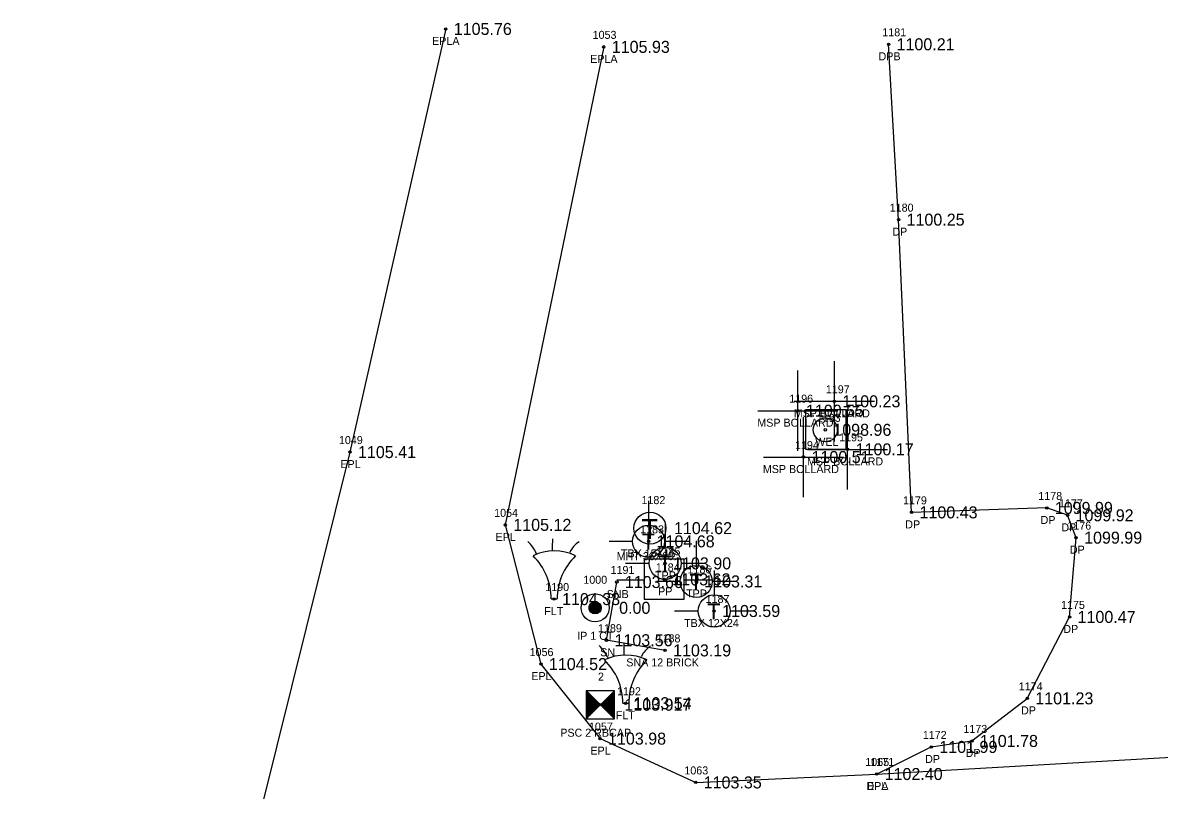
# Model space of a CAD drawing. Extents: x 1539151 to 1541799, y 1198646 to 1201165.
# Drawn here: x 1539356.2 to 1539498.1, y 1199362.1 to 1199457.9 of the extents above; entities that cross this region are included whole.
import ezdxf

# ---------------------------------------------------------------- set-up
doc = ezdxf.new("R2010")
doc.units = 0
for name, color, linetype in [('RD_EX_BldgApp', 7, 'Continuous'), ('RD_EX_BldgApp_txCode', 7, 'Continuous'), ('RD_EX_Driveway', 7, 'Continuous'), ('RD_EX_Driveway_txCode', 7, 'Continuous'), ('RD_EX_DV_Prop_txCode', 7, 'Continuous'), ('RD_EX_DV_PropPin', 7, 'Continuous'), ('RD_EX_Misc', 7, 'Continuous'), ('RD_EX_Misc_txCode', 7, 'Continuous'), ('RD_EX_Road', 7, 'Continuous'), ('RD_EX_Road_txCode', 7, 'Continuous'), ('RD_EX_SU_H2O', 7, 'Continuous'), ('RD_EX_SU_Telecom', 7, 'Continuous'), ('RD_EX_TX_BldgApp_ELEV', 7, 'Continuous'), ('RD_EX_TX_Driveway_ELEV', 7, 'Continuous'), ('RD_EX_TX_DV_Prop_ELEV', 7, 'Continuous'), ('RD_EX_TX_Misc_ELEV', 7, 'Continuous'), ('RD_EX_TX_Road_ELEV', 7, 'Continuous'), ('RD_EX_TX_UT_ELEV', 7, 'Continuous'), ('RD_EX_UT', 7, 'Continuous'), ('RD_EX_UT_txCode', 7, 'Continuous'), ('RD_HC_Survey', 7, 'Continuous'), ('RD_HC_Survey_ELEV', 7, 'Continuous'), ('RD_HC_txCode', 7, 'Continuous'), ('RD_SMD_Locator', 7, 'Continuous')]:
    doc.layers.add(name, color=color, linetype=linetype)

msp = doc.modelspace()

# ---------------------------------------------------------------- linework, layer by layer
at = {"layer": 'RD_EX_BldgApp'}
for p, q in [((1539422.2, 1199385.98), (1539422.95, 1199385.98)), ((1539431.13, 1199372.97), (1539431.88, 1199372.97))]:
    msp.add_line(p, q, dxfattribs=at)
msp.add_lwpolyline([(1539436.42, 1199379.55), (1539429.1, 1199380.82), (1539430.39, 1199388.09)], dxfattribs=at)
for centre, radius, start, end in [((1539384.5, 1199393.32), 37.88, 358.0671, 0.2715), ((1539415.89, 1199389.62), 4.89, 24.3279, 46.2665), ((1539422.58, 1199385.98), 6, 63.7794, 116.2206), ((1539427.47, 1199390.37), 3.28, 123.2906, 154.4886), ((1539414.7, 1199385.98), 7.5, 0, 45.8366), ((1539430.45, 1199385.98), 7.5, 134.1634, 180), ((1539393.43, 1199380.3), 37.88, 358.0671, 0.2715), ((1539424.82, 1199376.61), 4.89, 24.3279, 46.2665), ((1539436.4, 1199377.36), 3.28, 123.2906, 154.4886), ((1539431.51, 1199372.97), 6, 63.7794, 116.2206), ((1539423.63, 1199372.97), 7.5, 0, 45.8366), ((1539439.38, 1199372.97), 7.5, 134.1634, 180)]:
    msp.add_arc(centre, radius, start, end, dxfattribs=at)
at = {"layer": 'RD_EX_BldgApp_txCode'}
msp.add_circle((1539456.43, 1199407.1), 0.15, dxfattribs=at)
at = {"layer": 'RD_EX_Driveway'}
msp.add_lwpolyline([(1539462.84, 1199364.11), (1539469.67, 1199367.49), (1539474.74, 1199368.24), (1539481.66, 1199373.56), (1539486.94, 1199383.73), (1539487.76, 1199393.63), (1539486.69, 1199396.42), (1539484.1, 1199397.34), (1539467.2, 1199396.79), (1539465.58, 1199433.35), (1539464.33, 1199455.25)], dxfattribs=at)
at = {"layer": 'RD_EX_DV_PropPin'}
for p, q in [((1539426.94, 1199384.67), (1539426.94, 1199385.07)), ((1539426.98, 1199384.57), (1539426.98, 1199385.17)), ((1539427.01, 1199384.5), (1539427.01, 1199385.24)), ((1539427.05, 1199384.44), (1539427.05, 1199385.3)), ((1539427.08, 1199384.4), (1539427.08, 1199385.35)), ((1539427.12, 1199384.36), (1539427.12, 1199385.39)), ((1539427.15, 1199384.32), (1539427.15, 1199385.42)), ((1539427.19, 1199384.29), (1539427.19, 1199385.45)), ((1539427.22, 1199384.26), (1539427.22, 1199385.48)), ((1539427.26, 1199384.24), (1539427.26, 1199385.51)), ((1539427.29, 1199384.21), (1539427.29, 1199385.53)), ((1539427.33, 1199384.2), (1539427.33, 1199385.55)), ((1539427.36, 1199384.18), (1539427.36, 1199385.56)), ((1539427.4, 1199384.16), (1539427.4, 1199385.58)), ((1539427.43, 1199384.15), (1539427.43, 1199385.59)), ((1539427.47, 1199384.14), (1539427.47, 1199385.6)), ((1539427.5, 1199384.13), (1539427.5, 1199385.61)), ((1539427.54, 1199384.12), (1539427.54, 1199385.62)), ((1539427.57, 1199384.12), (1539427.57, 1199385.62)), ((1539427.61, 1199384.11), (1539427.61, 1199385.63)), ((1539427.64, 1199384.11), (1539427.64, 1199385.63)), ((1539427.68, 1199384.11), (1539427.68, 1199385.63)), ((1539427.71, 1199384.11), (1539427.71, 1199385.63)), ((1539427.75, 1199384.11), (1539427.75, 1199385.63)), ((1539427.78, 1199384.12), (1539427.78, 1199385.62)), ((1539427.82, 1199384.12), (1539427.82, 1199385.62)), ((1539427.85, 1199384.13), (1539427.85, 1199385.61)), ((1539427.89, 1199384.14), (1539427.89, 1199385.6)), ((1539427.92, 1199384.15), (1539427.92, 1199385.59)), ((1539427.96, 1199384.16), (1539427.96, 1199385.58)), ((1539427.99, 1199384.18), (1539427.99, 1199385.56)), ((1539428.03, 1199384.2), (1539428.03, 1199385.55)), ((1539428.06, 1199384.21), (1539428.06, 1199385.53)), ((1539428.1, 1199384.24), (1539428.1, 1199385.51)), ((1539428.13, 1199384.26), (1539428.13, 1199385.48)), ((1539428.17, 1199384.29), (1539428.17, 1199385.45)), ((1539428.2, 1199384.32), (1539428.2, 1199385.42)), ((1539428.24, 1199384.36), (1539428.24, 1199385.39)), ((1539428.27, 1199384.4), (1539428.27, 1199385.35)), ((1539428.31, 1199384.44), (1539428.31, 1199385.3)), ((1539428.34, 1199384.5), (1539428.34, 1199385.24)), ((1539428.38, 1199384.57), (1539428.38, 1199385.17)), ((1539428.41, 1199384.67), (1539428.41, 1199385.07))]:
    msp.add_line(p, q, dxfattribs=at)
for radius in [1.75, 0.761]:
    msp.add_circle((1539427.68, 1199384.87), radius, dxfattribs=at)
at = {"layer": 'RD_EX_Misc'}
for p, q in [((1539457.56, 1199405.66), (1539457.56, 1199415.66)), ((1539453.01, 1199404.49), (1539453.01, 1199414.49)), ((1539452.56, 1199410.66), (1539462.56, 1199410.66)), ((1539448.01, 1199409.49), (1539458.01, 1199409.49)), ((1539459.22, 1199399.66), (1539459.22, 1199409.66)), ((1539453.71, 1199398.7), (1539453.71, 1199408.7)), ((1539454.22, 1199404.66), (1539464.22, 1199404.66)), ((1539448.71, 1199403.7), (1539458.71, 1199403.7))]:
    msp.add_line(p, q, dxfattribs=at)
at = {"layer": 'RD_EX_Road'}
for points in [[(1539409.02, 1199457.17), (1539397.06, 1199404.32), (1539384.29, 1199353.07), (1539370.25, 1199298.34), (1539356.18, 1199244.03)], [(1539428.76, 1199454.93), (1539416.46, 1199395.23), (1539420.91, 1199377.84), (1539428.29, 1199368.53), (1539440.24, 1199363.06), (1539462.84, 1199364.11), (1539506.12, 1199366.59), (1539554.03, 1199368.02), (1539606.53, 1199370.48), (1539651.89, 1199372.76), (1539672.94, 1199372.91), (1539707.02, 1199374.85), (1539748.7, 1199377.62), (1539769.05, 1199378.19), (1539812.94, 1199380.16), (1539830.48, 1199381.23), (1539857.01, 1199382.87), (1539908.22, 1199385.45), (1539955.82, 1199389.74), (1539996.13, 1199397.4), (1540037.85, 1199410.51), (1540050.26, 1199415.61), (1540093.12, 1199444.78)]]:
    msp.add_lwpolyline(points, dxfattribs=at)
at = {"layer": 'RD_EX_SU_H2O'}
msp.add_lwpolyline([(1539453.98, 1199404.63), (1539453.98, 1199409.63), (1539458.98, 1199409.63), (1539458.98, 1199404.63)], close=True, dxfattribs=at)
msp.add_circle((1539456.43, 1199407.1), 1.5, dxfattribs=at)
at = {"layer": 'RD_EX_SU_Telecom'}
msp.add_circle((1539434.53, 1199394.82), 2, dxfattribs=at)
at = {"layer": 'RD_EX_UT'}
for p, q in [((1539434.36, 1199398.24), (1539434.36, 1199395.17)), ((1539436.42, 1199395.49), (1539436.42, 1199392.42)), ((1539440.31, 1199393.23), (1539440.31, 1199390.16)), ((1539429.43, 1199393.19), (1539432.36, 1199393.19)), ((1539436.36, 1199393.19), (1539439.43, 1199393.19)), ((1539431.49, 1199390.44), (1539434.42, 1199390.44)), ((1539438.82, 1199390.93), (1539433.82, 1199390.93)), ((1539433.82, 1199390.93), (1539433.82, 1199385.93)), ((1539438.42, 1199390.44), (1539441.49, 1199390.44)), ((1539438.82, 1199385.93), (1539438.82, 1199390.93)), ((1539442.54, 1199389.53), (1539442.54, 1199386.47)), ((1539430.39, 1199388.36), (1539433.86, 1199388.36)), ((1539435.38, 1199388.18), (1539438.31, 1199388.18)), ((1539438.75, 1199388.36), (1539442.39, 1199388.36)), ((1539442.31, 1199388.18), (1539445.38, 1199388.18)), ((1539433.82, 1199385.93), (1539438.82, 1199385.93)), ((1539437.61, 1199384.48), (1539440.54, 1199384.48)), ((1539444.54, 1199384.48), (1539447.61, 1199384.48))]:
    msp.add_line(p, q, dxfattribs=at)
for centre in [(1539434.36, 1199393.17), (1539436.42, 1199390.42), (1539440.31, 1199388.16), (1539442.54, 1199384.47)]:
    msp.add_circle(centre, 2, dxfattribs=at)
at = {"layer": 'RD_HC_Survey'}
for p, q in [((1539426.58, 1199374.52), (1539430.08, 1199371.02)), ((1539430.08, 1199374.52), (1539426.58, 1199371.02)), ((1539426.6, 1199374.49), (1539426.6, 1199371.04)), ((1539426.63, 1199374.47), (1539426.63, 1199371.07)), ((1539426.65, 1199374.44), (1539426.65, 1199371.09)), ((1539426.68, 1199374.42), (1539426.68, 1199371.12)), ((1539426.7, 1199374.39), (1539426.7, 1199371.14)), ((1539426.73, 1199374.37), (1539426.73, 1199371.17)), ((1539426.75, 1199374.34), (1539426.75, 1199371.19)), ((1539426.78, 1199374.32), (1539426.78, 1199371.21)), ((1539426.8, 1199374.29), (1539426.8, 1199371.24)), ((1539426.83, 1199374.27), (1539426.83, 1199371.26)), ((1539426.85, 1199374.24), (1539426.85, 1199371.29)), ((1539426.87, 1199374.22), (1539426.87, 1199371.31)), ((1539426.9, 1199374.2), (1539426.9, 1199371.34)), ((1539426.92, 1199374.17), (1539426.92, 1199371.36)), ((1539426.95, 1199374.15), (1539426.95, 1199371.39)), ((1539426.97, 1199374.12), (1539426.97, 1199371.41)), ((1539427, 1199374.1), (1539427, 1199371.44)), ((1539427.02, 1199374.07), (1539427.02, 1199371.46)), ((1539427.05, 1199374.05), (1539427.05, 1199371.49)), ((1539427.07, 1199374.02), (1539427.07, 1199371.51)), ((1539427.1, 1199374), (1539427.1, 1199371.54)), ((1539427.12, 1199373.97), (1539427.12, 1199371.56)), ((1539427.15, 1199373.95), (1539427.15, 1199371.59)), ((1539427.17, 1199373.92), (1539427.17, 1199371.61)), ((1539427.2, 1199373.9), (1539427.2, 1199371.64)), ((1539427.22, 1199373.87), (1539427.22, 1199371.66)), ((1539427.25, 1199373.85), (1539427.25, 1199371.69)), ((1539427.27, 1199373.82), (1539427.27, 1199371.71)), ((1539427.3, 1199373.8), (1539427.3, 1199371.73)), ((1539427.32, 1199373.77), (1539427.32, 1199371.76)), ((1539427.35, 1199373.75), (1539427.35, 1199371.78)), ((1539427.37, 1199373.73), (1539427.37, 1199371.81)), ((1539427.39, 1199373.7), (1539427.39, 1199371.83)), ((1539427.42, 1199373.68), (1539427.42, 1199371.86)), ((1539427.44, 1199373.65), (1539427.44, 1199371.88)), ((1539427.47, 1199373.63), (1539427.47, 1199371.91)), ((1539427.49, 1199373.6), (1539427.49, 1199371.93)), ((1539427.52, 1199373.58), (1539427.52, 1199371.96)), ((1539427.54, 1199373.55), (1539427.54, 1199371.98)), ((1539427.57, 1199373.53), (1539427.57, 1199372.01)), ((1539427.59, 1199373.5), (1539427.59, 1199372.03)), ((1539427.62, 1199373.48), (1539427.62, 1199372.06)), ((1539427.64, 1199373.45), (1539427.64, 1199372.08)), ((1539427.67, 1199373.43), (1539427.67, 1199372.11)), ((1539427.69, 1199373.4), (1539427.69, 1199372.13)), ((1539427.72, 1199373.38), (1539427.72, 1199372.16)), ((1539427.74, 1199373.35), (1539427.74, 1199372.18)), ((1539428.91, 1199373.35), (1539428.91, 1199372.18)), ((1539428.94, 1199373.38), (1539428.94, 1199372.16)), ((1539428.96, 1199373.4), (1539428.96, 1199372.13)), ((1539428.99, 1199373.43), (1539428.99, 1199372.11)), ((1539429.01, 1199373.45), (1539429.01, 1199372.08)), ((1539429.04, 1199373.48), (1539429.04, 1199372.06)), ((1539429.06, 1199373.5), (1539429.06, 1199372.03)), ((1539429.09, 1199373.53), (1539429.09, 1199372.01)), ((1539429.11, 1199373.55), (1539429.11, 1199371.98)), ((1539429.14, 1199373.58), (1539429.14, 1199371.96)), ((1539429.16, 1199373.6), (1539429.16, 1199371.93)), ((1539429.19, 1199373.63), (1539429.19, 1199371.91)), ((1539429.21, 1199373.65), (1539429.21, 1199371.88)), ((1539429.24, 1199373.68), (1539429.24, 1199371.86)), ((1539429.26, 1199373.7), (1539429.26, 1199371.83)), ((1539429.29, 1199373.73), (1539429.29, 1199371.81)), ((1539429.31, 1199373.75), (1539429.31, 1199371.78)), ((1539429.34, 1199373.77), (1539429.34, 1199371.76)), ((1539429.36, 1199373.8), (1539429.36, 1199371.73)), ((1539429.39, 1199373.82), (1539429.39, 1199371.71)), ((1539429.41, 1199373.85), (1539429.41, 1199371.69)), ((1539429.43, 1199373.87), (1539429.43, 1199371.66)), ((1539429.46, 1199373.9), (1539429.46, 1199371.64)), ((1539429.48, 1199373.92), (1539429.48, 1199371.61)), ((1539429.51, 1199373.95), (1539429.51, 1199371.59)), ((1539429.53, 1199373.97), (1539429.53, 1199371.56)), ((1539429.56, 1199374), (1539429.56, 1199371.54)), ((1539429.58, 1199374.02), (1539429.58, 1199371.51)), ((1539429.61, 1199374.05), (1539429.61, 1199371.49)), ((1539429.63, 1199374.07), (1539429.63, 1199371.46)), ((1539429.66, 1199374.1), (1539429.66, 1199371.44)), ((1539429.68, 1199374.12), (1539429.68, 1199371.41)), ((1539429.71, 1199374.15), (1539429.71, 1199371.39)), ((1539429.73, 1199374.17), (1539429.73, 1199371.36)), ((1539429.76, 1199374.2), (1539429.76, 1199371.34)), ((1539429.78, 1199374.22), (1539429.78, 1199371.31)), ((1539429.81, 1199374.24), (1539429.81, 1199371.29)), ((1539429.83, 1199374.27), (1539429.83, 1199371.26)), ((1539429.86, 1199374.29), (1539429.86, 1199371.24)), ((1539429.88, 1199374.32), (1539429.88, 1199371.21)), ((1539429.9, 1199374.34), (1539429.9, 1199371.19)), ((1539429.93, 1199374.37), (1539429.93, 1199371.17)), ((1539429.95, 1199374.39), (1539429.95, 1199371.14)), ((1539429.98, 1199374.42), (1539429.98, 1199371.12)), ((1539430, 1199374.44), (1539430, 1199371.09)), ((1539430.03, 1199374.47), (1539430.03, 1199371.07)), ((1539430.05, 1199374.49), (1539430.05, 1199371.04)), ((1539427.77, 1199373.33), (1539427.77, 1199372.2)), ((1539427.79, 1199373.3), (1539427.79, 1199372.23)), ((1539427.82, 1199373.28), (1539427.82, 1199372.25)), ((1539427.84, 1199373.25), (1539427.84, 1199372.28)), ((1539427.86, 1199373.23), (1539427.86, 1199372.3)), ((1539427.89, 1199373.21), (1539427.89, 1199372.33)), ((1539427.91, 1199373.18), (1539427.91, 1199372.35)), ((1539427.94, 1199373.16), (1539427.94, 1199372.38)), ((1539427.96, 1199373.13), (1539427.96, 1199372.4)), ((1539427.99, 1199373.11), (1539427.99, 1199372.43)), ((1539428.01, 1199373.08), (1539428.01, 1199372.45)), ((1539428.04, 1199373.06), (1539428.04, 1199372.48)), ((1539428.06, 1199373.03), (1539428.06, 1199372.5)), ((1539428.09, 1199373.01), (1539428.09, 1199372.53)), ((1539428.11, 1199372.98), (1539428.11, 1199372.55)), ((1539428.14, 1199372.96), (1539428.14, 1199372.58)), ((1539428.16, 1199372.93), (1539428.16, 1199372.6)), ((1539428.19, 1199372.91), (1539428.19, 1199372.63)), ((1539428.21, 1199372.88), (1539428.21, 1199372.65)), ((1539428.24, 1199372.86), (1539428.24, 1199372.68)), ((1539428.26, 1199372.83), (1539428.26, 1199372.7)), ((1539428.29, 1199372.81), (1539428.29, 1199372.72)), ((1539428.31, 1199372.78), (1539428.31, 1199372.75)), ((1539428.35, 1199372.78), (1539428.35, 1199372.75)), ((1539428.37, 1199372.81), (1539428.37, 1199372.72)), ((1539428.4, 1199372.83), (1539428.4, 1199372.7)), ((1539428.42, 1199372.86), (1539428.42, 1199372.68)), ((1539428.44, 1199372.88), (1539428.44, 1199372.65)), ((1539428.47, 1199372.91), (1539428.47, 1199372.63)), ((1539428.49, 1199372.93), (1539428.49, 1199372.6)), ((1539428.52, 1199372.96), (1539428.52, 1199372.58)), ((1539428.54, 1199372.98), (1539428.54, 1199372.55)), ((1539428.57, 1199373.01), (1539428.57, 1199372.53)), ((1539428.59, 1199373.03), (1539428.59, 1199372.5)), ((1539428.62, 1199373.06), (1539428.62, 1199372.48)), ((1539428.64, 1199373.08), (1539428.64, 1199372.45)), ((1539428.67, 1199373.11), (1539428.67, 1199372.43)), ((1539428.69, 1199373.13), (1539428.69, 1199372.4)), ((1539428.72, 1199373.16), (1539428.72, 1199372.38)), ((1539428.74, 1199373.18), (1539428.74, 1199372.35)), ((1539428.77, 1199373.21), (1539428.77, 1199372.33)), ((1539428.79, 1199373.23), (1539428.79, 1199372.3)), ((1539428.82, 1199373.25), (1539428.82, 1199372.28)), ((1539428.84, 1199373.28), (1539428.84, 1199372.25)), ((1539428.87, 1199373.3), (1539428.87, 1199372.23)), ((1539428.89, 1199373.33), (1539428.89, 1199372.2))]:
    msp.add_line(p, q, dxfattribs=at)
msp.add_lwpolyline([(1539430.08, 1199374.52), (1539426.58, 1199374.52), (1539426.58, 1199371.02), (1539430.08, 1199371.02)], close=True, dxfattribs=at)
at = {"layer": 'RD_SMD_Locator'}
for centre in [(1539409.02, 1199457.17), (1539428.76, 1199454.93), (1539464.33, 1199455.25), (1539465.58, 1199433.35), (1539457.56, 1199410.66), (1539453.01, 1199409.49), (1539459.22, 1199404.66), (1539397.06, 1199404.32), (1539453.71, 1199403.7), (1539467.2, 1199396.79), (1539484.1, 1199397.34), (1539486.69, 1199396.42), (1539416.46, 1199395.23), (1539434.53, 1199394.82), (1539434.36, 1199393.17), (1539487.76, 1199393.63), (1539436.42, 1199390.42), (1539430.39, 1199388.09), (1539436.33, 1199388.42), (1539440.31, 1199388.16), (1539422.55, 1199385.96), (1539427.68, 1199384.87), (1539442.54, 1199384.47), (1539486.94, 1199383.73), (1539429.1, 1199380.82), (1539436.42, 1199379.55), (1539420.91, 1199377.84), (1539481.66, 1199373.56), (1539428.33, 1199372.77), (1539431.48, 1199372.95), (1539428.29, 1199368.53), (1539474.74, 1199368.24), (1539469.67, 1199367.49), (1539462.84, 1199364.11), (1539462.84, 1199364.11), (1539440.24, 1199363.06)]:
    msp.add_circle(centre, 0.15, dxfattribs=at)

# ---------------------------------------------------------------- texts
at = {"layer": 'RD_EX_BldgApp_txCode'}
for s, p in [('1193', (1539455.37, 1199408.1)), ('WEL', (1539455.17, 1199405.1)), ('1191', (1539429.61, 1199389.09)), ('1190', (1539421.45, 1199386.96)), ('SNB', (1539429.13, 1199386.09)), ('FLT', (1539421.33, 1199383.96)), ('1189', (1539428.04, 1199381.82)), ('1188', (1539435.36, 1199380.55)), ('SN', (1539428.32, 1199378.82)), ('SNA 12 BRICK', (1539431.57, 1199377.55)), ('1192', (1539430.42, 1199373.95)), ('FLT', (1539430.26, 1199370.95))]:
    msp.add_text(s, height=1, dxfattribs=at).set_placement(p)
at = {"layer": 'RD_EX_Driveway_txCode'}
for s, p in [('1181', (1539463.55, 1199456.25)), ('DPB', (1539463.08, 1199453.25)), ('1180', (1539464.48, 1199434.35)), ('DP', (1539464.8, 1199431.35)), ('1178', (1539483.04, 1199398.34)), ('1179', (1539466.14, 1199397.79)), ('1177', (1539485.62, 1199397.42)), ('DP', (1539483.32, 1199395.34)), ('DP', (1539466.42, 1199394.79)), ('DP', (1539485.91, 1199394.42)), ('1176', (1539486.67, 1199394.63)), ('DP', (1539486.98, 1199391.63)), ('1175', (1539485.88, 1199384.73)), ('DP', (1539486.16, 1199381.73)), ('1174', (1539480.6, 1199374.56)), ('DP', (1539480.88, 1199371.56)), ('1172', (1539468.61, 1199368.49)), ('1173', (1539473.68, 1199369.24)), ('DP', (1539468.9, 1199365.49)), ('DP', (1539473.96, 1199366.24)), ('1171', (1539462.06, 1199365.11)), ('DPA', (1539461.57, 1199362.11))]:
    msp.add_text(s, height=1, dxfattribs=at).set_placement(p)
at = {"layer": 'RD_EX_DV_Prop_txCode'}
for s, p in [('1000', (1539426.21, 1199387.87)), ('IP 1 CT', (1539425.44, 1199380.87))]:
    msp.add_text(s, height=1, dxfattribs=at).set_placement(p)
at = {"layer": 'RD_EX_Misc_txCode'}
for s, p in [('1197', (1539456.5, 1199411.66)), ('1196', (1539451.93, 1199410.49)), ('MSP BOLLARD', (1539452.49, 1199408.66)), ('MSP BOLLARD', (1539447.94, 1199407.49)), ('1195', (1539458.16, 1199405.66)), ('1194', (1539452.65, 1199404.7)), ('MSP BOLLARD', (1539454.14, 1199402.66)), ('MSP BOLLARD', (1539448.63, 1199401.7))]:
    msp.add_text(s, height=1, dxfattribs=at).set_placement(p)
at = {"layer": 'RD_EX_Road_txCode'}
for s, p in [('EPLA', (1539407.32, 1199455.17)), ('1053', (1539427.37, 1199455.93)), ('EPLA', (1539427.06, 1199452.93)), ('1049', (1539395.68, 1199405.32)), ('EPL', (1539395.86, 1199402.32)), ('1054', (1539415.07, 1199396.23)), ('EPL', (1539415.25, 1199393.23)), ('1056', (1539419.5, 1199378.84)), ('EPL', (1539419.71, 1199375.84)), ('1057', (1539426.91, 1199369.53)), ('EPL', (1539427.09, 1199366.53)), ('1063', (1539438.83, 1199364.06)), ('1065', (1539461.43, 1199365.11)), ('EPL', (1539461.64, 1199362.11))]:
    msp.add_text(s, height=1, dxfattribs=at).set_placement(p)
at = {"layer": 'RD_EX_SU_Telecom'}
msp.add_text('T', height=2.5, dxfattribs=at).set_placement((1539433.47, 1199393.45))
at = {"layer": 'RD_EX_TX_BldgApp_ELEV'}
for s, p in [('1098.96', (1539457.43, 1199406.35)), ('1103.66', (1539431.39, 1199387.34)), ('1104.33', (1539423.55, 1199385.21)), ('1103.56', (1539430.1, 1199380.07)), ('1103.19', (1539437.42, 1199378.8)), ('1103.54', (1539432.48, 1199372.2))]:
    msp.add_text(s, height=1.5, dxfattribs=at).set_placement(p)
at = {"layer": 'RD_EX_TX_Driveway_ELEV'}
for s, p in [('1100.21', (1539465.33, 1199454.5)), ('1100.25', (1539466.58, 1199432.6)), ('1100.43', (1539468.2, 1199396.04)), ('1099.99', (1539485.1, 1199396.59)), ('1099.92', (1539487.69, 1199395.67)), ('1099.99', (1539488.76, 1199392.88)), ('1100.47', (1539487.94, 1199382.98)), ('1101.23', (1539482.66, 1199372.81)), ('1101.99', (1539470.67, 1199366.74)), ('1101.78', (1539475.74, 1199367.49)), ('1102.40', (1539463.84, 1199363.36))]:
    msp.add_text(s, height=1.5, dxfattribs=at).set_placement(p)
at = {"layer": 'RD_EX_TX_DV_Prop_ELEV'}
msp.add_text('0.00', height=1.5, dxfattribs=at).set_placement((1539430.68, 1199384.12))
at = {"layer": 'RD_EX_TX_Misc_ELEV'}
for s, p in [('1100.23', (1539458.56, 1199409.91)), ('1100.55', (1539454.01, 1199408.74)), ('1100.17', (1539460.22, 1199403.91)), ('1100.51', (1539454.71, 1199402.95))]:
    msp.add_text(s, height=1.5, dxfattribs=at).set_placement(p)
at = {"layer": 'RD_EX_TX_Road_ELEV'}
for s, p in [('1105.76', (1539410.02, 1199456.42)), ('1105.93', (1539429.76, 1199454.18)), ('1105.41', (1539398.06, 1199403.57)), ('1105.12', (1539417.46, 1199394.48)), ('1104.52', (1539421.91, 1199377.09)), ('1103.98', (1539429.29, 1199367.78)), ('1102.40', (1539463.84, 1199363.36)), ('1103.35', (1539441.24, 1199362.31))]:
    msp.add_text(s, height=1.5, dxfattribs=at).set_placement(p)
at = {"layer": 'RD_EX_TX_UT_ELEV'}
for s, p in [('1104.62', (1539437.53, 1199394.07)), ('1104.68', (1539435.36, 1199392.42)), ('1103.90', (1539437.42, 1199389.67)), ('1103.31', (1539441.31, 1199387.41)), ('1103.59', (1539443.54, 1199383.72))]:
    msp.add_text(s, height=1.5, dxfattribs=at).set_placement(p)
at = {"layer": 'RD_EX_UT'}
for p in [(1539433.51, 1199392.13), (1539435.58, 1199389.38), (1539439.46, 1199387.12), (1539441.69, 1199383.42)]:
    msp.add_text('T', height=2, dxfattribs=at).set_placement(p)
at = {"layer": 'RD_EX_UT_txCode'}
for s, p in [('1182', (1539433.47, 1199397.82)), ('1183', (1539433.3, 1199394.17)), ('MHT 36X60', (1539430.37, 1199390.82)), ('TBX 15X15', (1539430.9, 1199391.17)), ('1185', (1539435.36, 1199391.42)), ('1184', (1539435.26, 1199389.42)), ('TPP', (1539435.16, 1199388.42)), ('1186', (1539439.22, 1199389.16)), ('PP', (1539435.55, 1199386.42)), ('TPP', (1539439.04, 1199386.16)), ('1187', (1539441.48, 1199385.47)), ('TBX 12X24', (1539438.79, 1199382.47))]:
    msp.add_text(s, height=1, dxfattribs=at).set_placement(p)
at = {"layer": 'RD_HC_Survey_ELEV'}
for s, p in [('1103.62', (1539437.33, 1199387.67)), ('1103.917', (1539431.33, 1199372.02))]:
    msp.add_text(s, height=1.5, dxfattribs=at).set_placement(p)
at = {"layer": 'RD_HC_txCode'}
for s, p in [('2', (1539428.04, 1199375.77)), ('PSC 2 RBCAP', (1539423.33, 1199368.77))]:
    msp.add_text(s, height=1, dxfattribs=at).set_placement(p)

doc.saveas('drawing.dxf')
